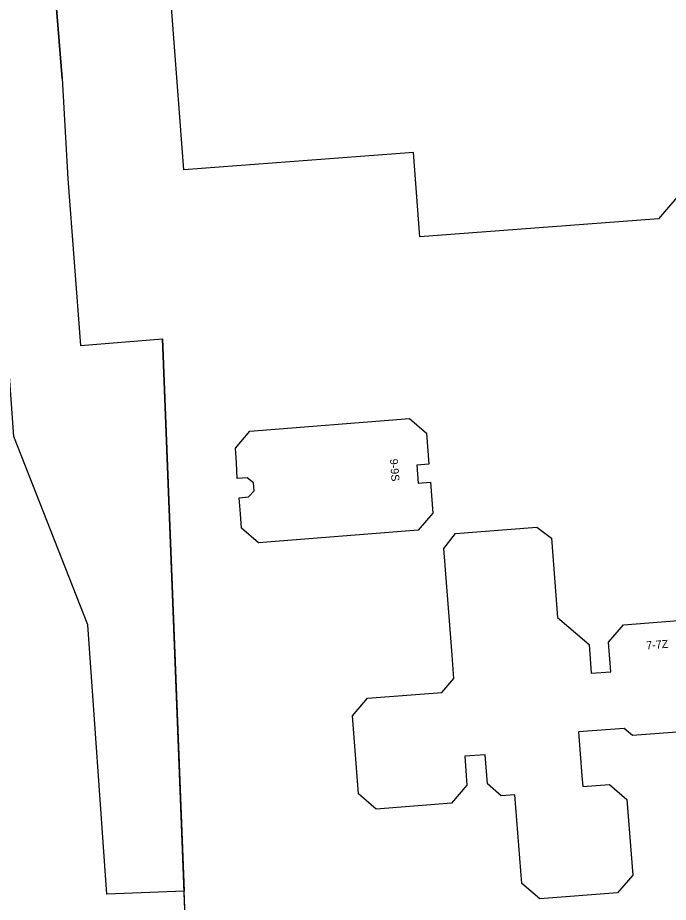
# Model space of a CAD drawing. Extents: x 157793 to 159380, y 380882 to 382313.
# Drawn here: x 158056.4 to 158137.7, y 380961.3 to 381071.7 of the extents above; entities that cross this region are included whole.
import ezdxf

# ---------------------------------------------------------------- set-up
doc = ezdxf.new("R2010")
doc.units = 0
for name, color, linetype in [('IMGEO_Groenvoorziening', 7, 'Continuous'), ('IMGEO_Hek', 7, 'Continuous'), ('IMGEO_Pand', 7, 'Continuous'), ('IMGEO_Pand_nummerreeks', 7, 'Continuous')]:
    doc.layers.add(name, color=color, linetype=linetype)

msp = doc.modelspace()

# ---------------------------------------------------------------- linework, layer by layer
at = {"layer": 'IMGEO_Groenvoorziening'}
for points in [[(158050.52, 381211.31), (158052.68, 381183.23), (158054.91, 381179.84), (158056.16, 381166.26), (158053.9, 381166.07), (158054.33, 381160.5), (158058.21, 381110.92), (158062.01, 381064.14), (158062.71, 381051.62), (158064.28, 381030.81), (158074.5, 381031.62), (158077.21, 380962.66)], [(158077.21, 380962.66), (158067.56, 380962.27), (158065.18, 380995.89), (158055.95, 381019.41), (158054.89, 381034.53), (158046.32, 381163.55), (158039.77, 381165.89), (158037.71, 381178.39)], [(158077.72, 380949.69), (158077.21, 380962.66)]]:
    msp.add_lwpolyline(points, dxfattribs=at)
at = {"layer": 'IMGEO_Hek'}
for points in [[(158062.01, 381064.14), (158058.21, 381110.92)], [(158077.72, 380949.69), (158074.5, 381031.62)]]:
    msp.add_lwpolyline(points, dxfattribs=at)
at = {"layer": 'IMGEO_Pand'}
for points in [[(158134.96, 381117.69), (158136.46, 381097.75), (158131.87, 381097.4), (158132.4, 381090.34), (158143.27, 381091.16), (158145.81, 381057.52), (158136.44, 381046.62), (158131.46, 381046.24), (158106.65, 381044.38), (158105.86, 381054.88), (158077.17, 381052.71), (158072.66, 381112.54), (158072.64, 381112.77)], [(158107.47, 381019.86), (158107.78, 381015.98), (158106.25, 381015.86), (158106.42, 381013.61), (158107.96, 381013.74), (158108.25, 381009.87), (158106.44, 381007.75), (158086.5, 381006.16), (158084.4, 381008), (158084.24, 381009.78), (158084.07, 381011.79), (158085.27, 381011.88), (158085.95, 381012.63), (158085.86, 381013.63), (158085.08, 381014.25), (158083.86, 381014.18), (158083.74, 381016.16), (158083.63, 381017.96), (158085.42, 381020.09), (158105.37, 381021.66), (158107.47, 381019.86)], [(158142.64, 380982.8), (158133.2, 380982.08), (158132.15, 380982.98), (158126.45, 380982.54), (158126.87, 380977.06), (158126.98, 380975.71), (158130.3, 380975.96), (158132.48, 380974.08), (158133.21, 380964.65), (158131.31, 380962.43), (158121.62, 380961.68), (158119.36, 380963.62), (158118.51, 380974.68), (158116.8, 380974.55), (158115.07, 380976.04), (158114.79, 380979.69), (158112.24, 380979.49), (158112.52, 380975.87), (158110.6, 380973.63), (158101.19, 380972.91), (158098.98, 380974.81), (158098.23, 380984.56), (158100.11, 380986.76), (158109.39, 380987.47), (158110.89, 380989.21), (158110.67, 380992.13), (158110.54, 380993.75), (158109.64, 381005.45), (158111.1, 381007.3), (158121.26, 381008.1), (158123.07, 381006.72)], [(158123.07, 381006.72), (158123.83, 380996.83), (158127.76, 380993.46), (158128.04, 380989.87), (158130.48, 380990.06), (158130.19, 380993.75), (158132.05, 380995.91), (158141.53, 380996.64)]]:
    msp.add_lwpolyline(points, dxfattribs=at)

# ---------------------------------------------------------------- texts
at = {"layer": 'IMGEO_Pand_nummerreeks'}
for s, rotation, p in [('9-9S', 274.3577, (158102.9, 381016.61)), ('7-7Z', 4.3889, (158134.94, 380992.84))]:
    msp.add_text(s, height=1, rotation=rotation, dxfattribs=at).set_placement(p)

doc.saveas('drawing.dxf')
